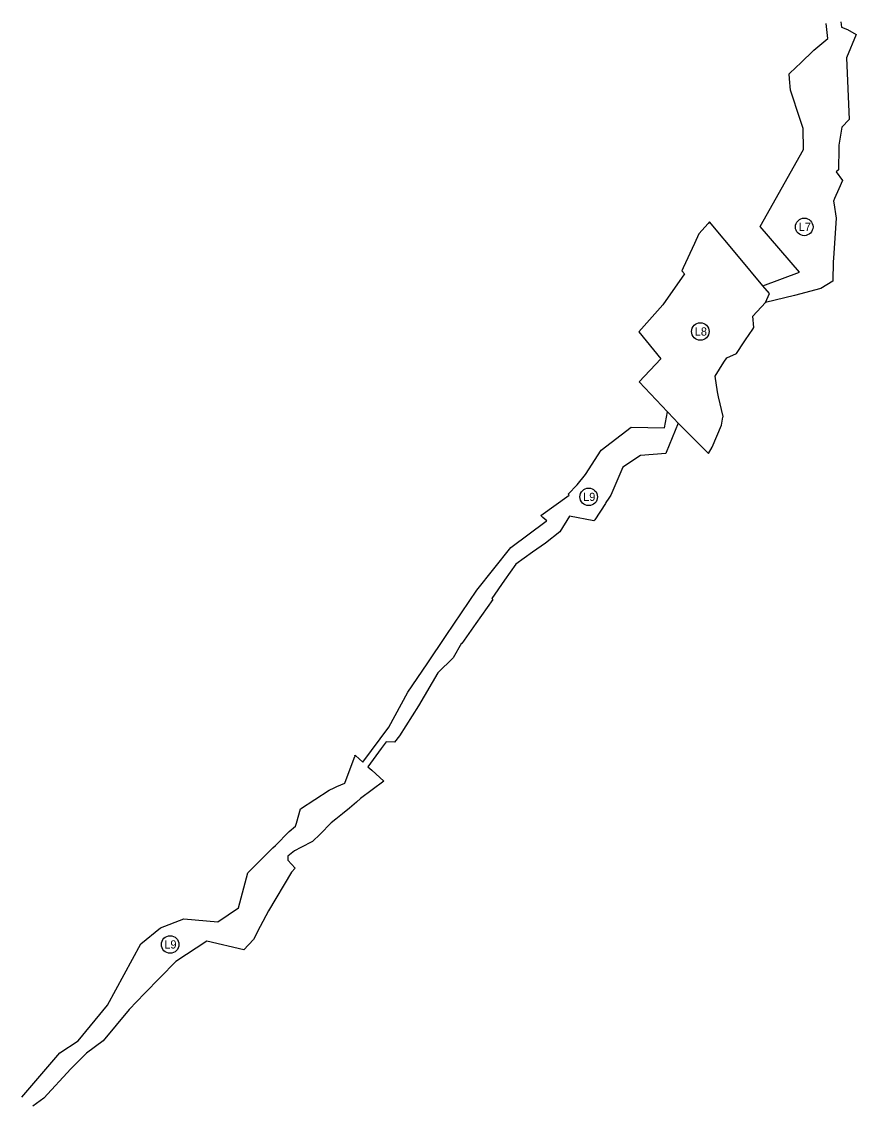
# Model space of a CAD drawing. Extents: x -445081 to -429827, y -1135509 to -1130100.
# Drawn here: x -443453 to -442234, y -1131685 to -1130100 of the extents above; entities that cross this region are included whole.
import ezdxf

# ---------------------------------------------------------------- set-up
doc = ezdxf.new("R2010")
doc.units = 0
for name, color, linetype in [('Vrstva 32', 7, 'Continuous'), ('Vrstva 33', 7, 'Continuous'), ('Vrstva 36', 7, 'Continuous')]:
    doc.layers.add(name, color=color, linetype=linetype)

msp = doc.modelspace()

# ---------------------------------------------------------------- linework, layer by layer
at = {"layer": 'Vrstva 32'}
for points in [[(-442500.4, -1130680), (-442494.3, -1130686.6), (-442450, -1130731.2), (-442444.7, -1130721.6), (-442431, -1130689.7), (-442428.9, -1130677.9), (-442428.3, -1130677.1), (-442435.4, -1130648.4), (-442436.5, -1130640.9), (-442440.2, -1130618), (-442427.6, -1130597.9), (-442423.1, -1130591.1), (-442409.1, -1130585), (-442397.6, -1130568), (-442395.7, -1130565.2), (-442385.3, -1130549.3), (-442383.6, -1130547), (-442385.3, -1130530.5), (-442366.4, -1130510.7), (-442360.9, -1130497.4), (-442370.7, -1130486.1), (-442406.2, -1130443.3), (-442448.5, -1130392.9), (-442450.5, -1130395.2), (-442463.8, -1130410.1), (-442470.3, -1130424.2), (-442486.8, -1130460), (-442488.8, -1130464.4), (-442485.1, -1130468.8), (-442516.4, -1130513.9), (-442551.6, -1130553.3), (-442519.2, -1130593), (-442551.2, -1130626.3), (-442509.5, -1130670.3), (-442500.4, -1130680)], [(-442494.3, -1130686.6), (-442450, -1130731.2), (-442444.7, -1130721.6), (-442431, -1130689.7), (-442428.9, -1130677.9), (-442428.3, -1130677.1), (-442435.4, -1130648.4), (-442436.5, -1130640.9), (-442440.2, -1130618), (-442427.6, -1130597.9), (-442423.1, -1130591.1), (-442409.1, -1130585), (-442397.6, -1130568), (-442395.7, -1130565.2), (-442385.3, -1130549.3), (-442383.6, -1130547), (-442385.3, -1130530.5), (-442366.4, -1130510.7), (-442360.9, -1130497.4), (-442370.7, -1130486.1), (-442406.2, -1130443.3), (-442448.5, -1130392.9), (-442450.5, -1130395.2), (-442463.8, -1130410.1), (-442470.3, -1130424.2), (-442486.8, -1130460), (-442488.8, -1130464.4), (-442485.1, -1130468.8), (-442516.4, -1130513.9), (-442551.6, -1130553.3), (-442519.2, -1130593), (-442551.2, -1130626.3), (-442509.5, -1130670.3), (-442500.4, -1130680), (-442494.3, -1130686.6)]]:
    msp.add_lwpolyline(points, dxfattribs=at)
at = {"layer": 'Vrstva 33'}
for points in [[(-442370.7, -1130486.1), (-442317.1, -1130466.2), (-442374.4, -1130399.5), (-442310.9, -1130287.1), (-442311.6, -1130256.5), (-442316.1, -1130243.3), (-442329.9, -1130200.5), (-442331.3, -1130183.6), (-442331.9, -1130176.7), (-442321.7, -1130167), (-442315.4, -1130161), (-442296, -1130142), (-442275.7, -1130125.1), (-442277.9, -1130102.8)], [(-442256.7, -1130100.4), (-442255.5, -1130108.3), (-442246.8, -1130112), (-442234, -1130119), (-442248.1, -1130153), (-442244.5, -1130243), (-442255.2, -1130254.4), (-442259.6, -1130280.6), (-442259.6, -1130284.4), (-442259.9, -1130316.5), (-442263.6, -1130319.6), (-442254.2, -1130332.4), (-442259.4, -1130344.3), (-442265.6, -1130358.6), (-442267.3, -1130362.3), (-442266.9, -1130365), (-442263.2, -1130387.1), (-442267.5, -1130445.7), (-442267.5, -1130446.1), (-442267.8, -1130450.6), (-442268.2, -1130479.5), (-442285.6, -1130490.3), (-442324.2, -1130500.2), (-442366.4, -1130510.7)], [(-442686.1, -1130829.2), (-442691.6, -1130824.4), (-442694.7, -1130821.7), (-442653.3, -1130791.8), (-442654.8, -1130790.5), (-442641.6, -1130776.9), (-442629.5, -1130761.6), (-442606.7, -1130726), (-442562.7, -1130692.5), (-442514.2, -1130693.4), (-442509.5, -1130670.3)], [(-442494.3, -1130686.6), (-442511.7, -1130729.7), (-442512.3, -1130731.3), (-442549, -1130734), (-442575.1, -1130750.9), (-442592.3, -1130791.8), (-442595.2, -1130796.2), (-442599.6, -1130802.8), (-442600.3, -1130803.9), (-442615.9, -1130827.9), (-442617.3, -1130829.5), (-442652.9, -1130822.4), (-442667, -1130845.3)], [(-443452.7, -1131671), (-443396.8, -1131606.2), (-443370.3, -1131589), (-443327.3, -1131537), (-443278.6, -1131447.3), (-443250.2, -1131423.9), (-443215.8, -1131410.9), (-443166.2, -1131415), (-443136, -1131394.6), (-443122.7, -1131343.5), (-443086.1, -1131307.1), (-443081.9, -1131303.5), (-443062, -1131283.2), (-443052.7, -1131275.2), (-443051.5, -1131270.9), (-443045.6, -1131250), (-443003.9, -1131223), (-442996.3, -1131219.2), (-442992.4, -1131217.4), (-442980.9, -1131212.4), (-442980.4, -1131211), (-442966.3, -1131173.8), (-442966, -1131172.9), (-442966.1, -1131171.8), (-442965.4, -1131172.2), (-442954.8, -1131181.7), (-442916.8, -1131130.9), (-442888.8, -1131079.5), (-442860.4, -1131038.3), (-442833, -1130996.7), (-442787.9, -1130930.9), (-442738.6, -1130868.5), (-442687, -1130829.9), (-442686.1, -1130829.2)], [(-442667, -1130845.3), (-442687.9, -1130861.8), (-442706.6, -1130875.3), (-442731.2, -1130892.6), (-442747.8, -1130916), (-442766.2, -1130942.8), (-442764.8, -1130944.2), (-442789.7, -1130979.4), (-442810.1, -1131008.8), (-442810.4, -1131008.2), (-442822.6, -1131029.3), (-442844.9, -1131051.5), (-442873.5, -1131099.5), (-442900.9, -1131143.2), (-442908.4, -1131152.6), (-442920.4, -1131152.4), (-442927.7, -1131161.9), (-442947.2, -1131188.6), (-442941.6, -1131193.6), (-442923.7, -1131209.8), (-442958.1, -1131234.8), (-442964, -1131240.5), (-442973.9, -1131249.1), (-442984.3, -1131257.3), (-442994.1, -1131265), (-443000.8, -1131270.7), (-443017.1, -1131286.9), (-443028.3, -1131297.9), (-443045.1, -1131306.6), (-443054.4, -1131311.4), (-443064.1, -1131319.2)], [(-443064.1, -1131319.2), (-443064.3, -1131325.2), (-443053.2, -1131336.6), (-443058.6, -1131342.7), (-443092.5, -1131399.2), (-443104.4, -1131422.1), (-443114.1, -1131440.9), (-443128.4, -1131456), (-443182.5, -1131443.5), (-443227.7, -1131473.1), (-443273.6, -1131519.9), (-443295.8, -1131542.9), (-443333.6, -1131588.9), (-443358.2, -1131607), (-443381.2, -1131630), (-443420.3, -1131672.4), (-443436.5, -1131684.5)]]:
    msp.add_lwpolyline(points, dxfattribs=at)
at = {"layer": 'Vrstva 36'}
for centre in [(-442310, -1130400.1), (-442461.7, -1130552.9), (-442624.7, -1130794.4), (-443236, -1131448.2)]:
    msp.add_circle(centre, 12.8, dxfattribs=at)

# ---------------------------------------------------------------- texts
for s, p in [('L7', (-442318.2, -1130406.1)), ('L8', (-442469.9, -1130558.9)), ('L9', (-442632.9, -1130800.4)), ('L9', (-443244.5, -1131454.1))]:
    msp.add_text(s, height=12, dxfattribs=at).set_placement(p)

doc.saveas('drawing.dxf')
